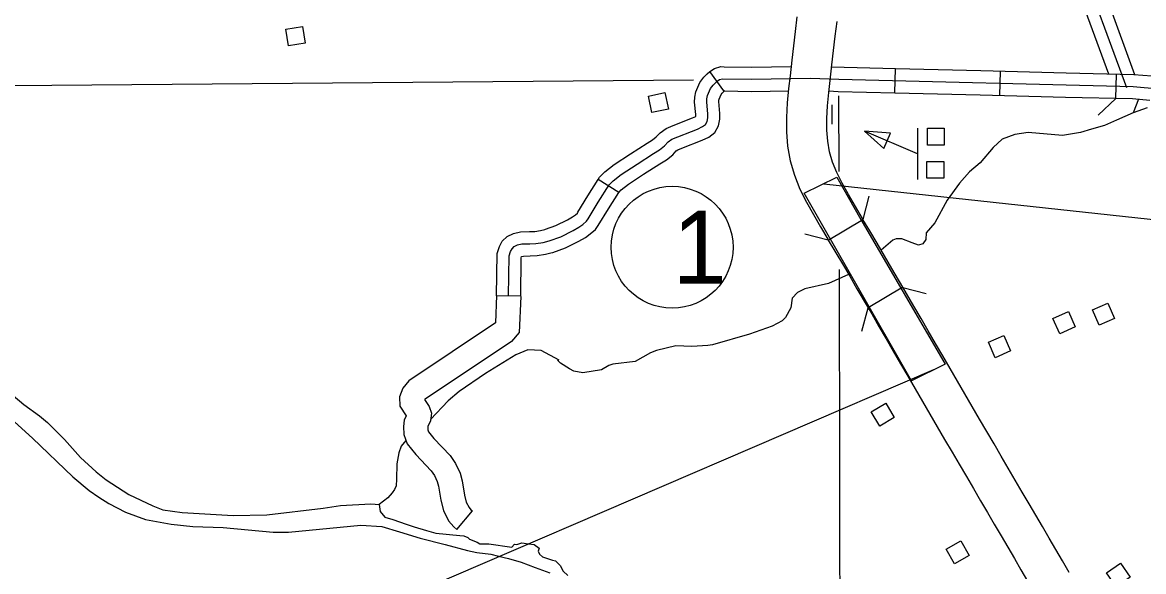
# Model space of a CAD drawing. Extents: x 1369885 to 1370219, y 379980 to 380218.
# Drawn here: x 1370027.37 to 1370054.99, y 380094.55 to 380108.07 of the extents above; entities that cross this region are included whole.
import ezdxf

# ---------------------------------------------------------------- set-up
doc = ezdxf.new("R2010")
doc.units = 0
for name, color, linetype in [('Default', 7, 'Continuous'), ('Level 10', 7, 'Continuous'), ('Level 32', 7, 'Continuous'), ('Level 35', 7, 'Continuous'), ('Level 37', 7, 'Continuous'), ('Level 38', 7, 'Continuous'), ('Level 45', 7, 'Continuous'), ('Level 46', 7, 'Continuous'), ('Level 5', 7, 'Continuous'), ('Level 56', 7, 'Continuous'), ('Page Text', 7, 'Continuous')]:
    doc.layers.add(name, color=color, linetype=linetype)

msp = doc.modelspace()

# ---------------------------------------------------------------- linework, layer by layer
at = {"layer": 'Default'}
msp.add_lwpolyline([(1370046.636, 380103.865), (1370047.441, 380104.259), (1370048.026, 380103.218), (1370050.106, 380099.662), (1370049.273, 380099.251)], close=True, dxfattribs=at)
msp.add_circle((1370043.38, 380102.537), 1.501, dxfattribs=at)
at = {"layer": 'Level 10'}
for points in [[(1370046.454, 380108.209), (1370046.412, 380107.854), (1370046.37, 380107.499), (1370046.328, 380107.147), (1370046.284, 380106.757), (1370046.25, 380106.446), (1370046.216, 380106.092), (1370046.196, 380105.734), (1370046.198, 380105.38), (1370046.226, 380105.025), (1370046.287, 380104.664), (1370046.391, 380104.309), (1370046.528, 380103.97), (1370046.69, 380103.651), (1370046.859, 380103.345), (1370047.034, 380103.042), (1370047.212, 380102.737), (1370047.227, 380102.712), (1370048.08, 380103.222)], [(1370048.08, 380103.222), (1370048.068, 380103.243), (1370047.894, 380103.542), (1370047.725, 380103.834), (1370047.569, 380104.116), (1370047.434, 380104.381), (1370047.332, 380104.636), (1370047.258, 380104.887), (1370047.214, 380105.148), (1370047.192, 380105.422), (1370047.191, 380105.71), (1370047.208, 380106.017), (1370047.239, 380106.345), (1370047.272, 380106.647), (1370047.316, 380107.033), (1370047.357, 380107.381), (1370047.4, 380107.737), (1370047.442, 380108.093)], [(1370049.064, 380101.551), (1370048.793, 380102.014), (1370048.613, 380102.326), (1370048.43, 380102.636), (1370048.248, 380102.942), (1370048.08, 380103.222)], [(1370047.227, 380102.712), (1370047.575, 380102.129), (1370047.754, 380101.824), (1370047.933, 380101.516), (1370048.207, 380101.046)], [(1370053.161, 380094.528), (1370052.999, 380094.812), (1370052.835, 380095.095), (1370052.672, 380095.377), (1370052.507, 380095.659), (1370052.341, 380095.94), (1370052.174, 380096.223), (1370052.004, 380096.51), (1370051.832, 380096.801), (1370051.661, 380097.094), (1370051.488, 380097.393), (1370051.311, 380097.697), (1370051.131, 380098.001), (1370050.952, 380098.305), (1370050.773, 380098.613), (1370050.593, 380098.926), (1370050.411, 380099.24), (1370050.228, 380099.552), (1370050.046, 380099.863), (1370049.867, 380100.17), (1370049.69, 380100.476), (1370049.512, 380100.782), (1370049.334, 380101.088), (1370049.154, 380101.397), (1370049.064, 380101.551), (1370048.207, 380101.046)], [(1370048.207, 380101.046), (1370048.296, 380100.895), (1370048.475, 380100.588), (1370048.652, 380100.282), (1370048.829, 380099.978), (1370049.007, 380099.67), (1370049.188, 380099.361), (1370049.37, 380099.05), (1370049.552, 380098.739), (1370049.732, 380098.428), (1370049.912, 380098.115), (1370050.094, 380097.803), (1370050.275, 380097.495), (1370050.453, 380097.194), (1370050.628, 380096.894), (1370050.801, 380096.594), (1370050.975, 380096.297), (1370051.148, 380096.005), (1370051.317, 380095.717), (1370051.485, 380095.434), (1370051.65, 380095.154), (1370051.812, 380094.877), (1370051.974, 380094.597), (1370052.137, 380094.316)]]:
    msp.add_lwpolyline(points, dxfattribs=at)
at = {"layer": 'Level 32'}
for p, q in [((1370048.87, 380106.341), (1370048.885, 380106.938)), ((1370051.451, 380106.277), (1370051.466, 380106.874)), ((1370054.31, 380106.2), (1370054.324, 380106.797))]:
    msp.add_line(p, q, dxfattribs=at)
for points in [[(1370047.31, 380106.977), (1370048.885, 380106.938)], [(1370048.885, 380106.938), (1370050.985, 380106.886)], [(1370050.985, 380106.886), (1370053.084, 380106.834)], [(1370046.778, 380106.702), (1370047.483, 380106.674), (1370054.738, 380106.495), (1370055.378, 380106.44)], [(1370053.084, 380106.834), (1370054.754, 380106.793), (1370055.2, 380106.755)], [(1370047.244, 380106.385), (1370047.473, 380106.376), (1370048.87, 380106.341)], [(1370048.87, 380106.341), (1370050.97, 380106.289)], [(1370050.97, 380106.289), (1370053.07, 380106.237)], [(1370053.07, 380106.237), (1370054.722, 380106.197), (1370055.15, 380106.16)]]:
    msp.add_lwpolyline(points, dxfattribs=at)
at = {"layer": 'Level 35'}
for points in [[(1370054.872, 380106.184), (1370054.735, 380105.847)], [(1370055.082, 380105.97), (1370054.735, 380105.847), (1370054.327, 380105.664), (1370054.028, 380105.535), (1370053.711, 380105.448), (1370053.437, 380105.365), (1370052.996, 380105.287), (1370052.151, 380105.365), (1370051.823, 380105.311), (1370051.513, 380105.202), (1370051.288, 380104.996), (1370050.966, 380104.615), (1370050.707, 380104.396), (1370050.457, 380104.117), (1370050.152, 380103.693), (1370049.851, 380103.142), (1370049.642, 380102.889), (1370049.633, 380102.728), (1370049.553, 380102.621), (1370049.446, 380102.586), (1370049.29, 380102.645), (1370049.037, 380102.747), (1370048.902, 380102.745), (1370048.821, 380102.711), (1370048.53, 380102.467)], [(1370047.729, 380101.868), (1370047.231, 380101.648), (1370046.651, 380101.514), (1370046.471, 380101.421), (1370046.341, 380101.282), (1370046.308, 380101.045), (1370046.172, 380100.81), (1370046.091, 380100.724), (1370045.845, 380100.597), (1370045.287, 380100.393), (1370044.373, 380100.138), (1370044.259, 380100.114), (1370043.866, 380100.09), (1370043.468, 380100.11), (1370042.995, 380099.996), (1370042.85, 380099.94), (1370042.471, 380099.721), (1370041.921, 380099.657), (1370041.823, 380099.626), (1370041.643, 380099.521), (1370041.181, 380099.447), (1370040.961, 380099.488), (1370040.852, 380099.54), (1370040.633, 380099.681), (1370040.555, 380099.76)], [(1370040.597, 380099.757), (1370040.157, 380099.997), (1370039.823, 380100.011), (1370039.529, 380099.89), (1370038.784, 380099.425), (1370038.13, 380098.987), (1370037.859, 380098.756), (1370037.43, 380098.297)], [(1370026.993, 380099.02), (1370027.405, 380098.662), (1370027.791, 380098.387), (1370027.99, 380098.221), (1370028.408, 380097.807), (1370028.807, 380097.361), (1370029.187, 380097.006), (1370029.439, 380096.806), (1370029.998, 380096.448), (1370030.583, 380096.167), (1370030.832, 380096.075), (1370031.307, 380096.002)], [(1370026.73, 380098.637), (1370027.62, 380097.839), (1370028.619, 380096.881), (1370029.014, 380096.55), (1370029.258, 380096.382), (1370029.501, 380096.226), (1370029.912, 380096.011), (1370030.402, 380095.831), (1370031.042, 380095.715), (1370031.575, 380095.663), (1370032.319, 380095.638), (1370033.554, 380095.52), (1370033.931, 380095.52), (1370035.714, 380095.697), (1370036.23, 380095.657), (1370036.662, 380095.53), (1370037.169, 380095.375), (1370037.791, 380095.219), (1370038.336, 380095.068), (1370038.569, 380095.023), (1370038.913, 380094.983), (1370039.103, 380094.931), (1370039.345, 380094.873), (1370039.657, 380094.781), (1370040.006, 380094.65), (1370040.369, 380094.518)], [(1370036.823, 380097.781), (1370036.702, 380097.636), (1370036.647, 380097.471), (1370036.596, 380097.206), (1370036.589, 380096.824), (1370036.584, 380096.666), (1370036.537, 380096.572), (1370036.484, 380096.493), (1370036.374, 380096.365), (1370036.166, 380096.199)], [(1370031.307, 380096.002), (1370032.564, 380095.932), (1370033.398, 380095.95), (1370034.783, 380096.114), (1370035.206, 380096.175), (1370035.959, 380096.222), (1370036.063, 380096.211), (1370036.166, 380096.199), (1370036.189, 380096.032), (1370036.305, 380095.894), (1370036.501, 380095.836), (1370036.827, 380095.715), (1370037.023, 380095.651), (1370037.329, 380095.559), (1370037.561, 380095.496), (1370038.147, 380095.438), (1370038.251, 380095.427), (1370038.345, 380095.386), (1370038.389, 380095.346), (1370038.573, 380095.277), (1370038.642, 380095.236), (1370038.867, 380095.236), (1370039.432, 380095.156), (1370039.493, 380095.227), (1370039.551, 380095.221), (1370039.676, 380095.258), (1370039.839, 380095.233), (1370039.983, 380095.221), (1370040.104, 380095.129), (1370040.081, 380095.054), (1370040.11, 380094.979), (1370040.19, 380094.91), (1370040.432, 380094.829), (1370040.507, 380094.812), (1370040.618, 380094.703), (1370040.694, 380094.562), (1370040.813, 380094.454)]]:
    msp.add_lwpolyline(points, dxfattribs=at)
at = {"layer": 'Level 37'}
for points in [[(1370048.23, 380103.798), (1370048.081, 380103.22)], [(1370047.225, 380102.714), (1370046.647, 380102.863)], [(1370049.065, 380101.549), (1370049.642, 380101.398)], [(1370048.054, 380100.47), (1370048.206, 380101.048)]]:
    msp.add_lwpolyline(points, dxfattribs=at)
at = {"layer": 'Level 38'}
for points in [[(1370054.324, 380106.797), (1370054.324, 380106.797)], [(1370054.31, 380106.2), (1370053.877, 380105.789)]]:
    msp.add_lwpolyline(points, dxfattribs=at)
at = {"layer": 'Level 45'}
for p, q in [((1370044.65, 380106.387), (1370044.307, 380106.867)), ((1370042.064, 380103.887), (1370041.557, 380104.202)), ((1370039.65, 380101.336), (1370039.053, 380101.343))]:
    msp.add_line(p, q, dxfattribs=at)
for points in [[(1370052.754, 380109.927), (1370053.05, 380109.996), (1370053.121, 380109.994), (1370053.246, 380109.934), (1370053.354, 380109.798), (1370054.57, 380106.474)], [(1370054.12, 380108.574), (1370054.771, 380106.792)], [(1370053.559, 380108.369), (1370054.13, 380106.808)], [(1370043.402, 380105.532), (1370043.884, 380105.721), (1370043.962, 380105.757), (1370043.962, 380105.758), (1370043.962, 380105.804), (1370043.933, 380106.109), (1370043.937, 380106.229), (1370043.966, 380106.367), (1370044.063, 380106.593), (1370044.161, 380106.726), (1370044.24, 380106.804), (1370044.307, 380106.867), (1370044.427, 380106.942), (1370044.582, 380106.985), (1370044.66, 380106.984)], [(1370044.66, 380106.984), (1370045.343, 380106.973), (1370046.311, 380106.991)], [(1370044.387, 380106.53), (1370044.447, 380106.589), (1370044.49, 380106.63), (1370044.548, 380106.666), (1370044.621, 380106.686), (1370045.343, 380106.674), (1370046.778, 380106.702)], [(1370039.351, 380101.339), (1370039.363, 380102.33), (1370039.398, 380102.434), (1370039.435, 380102.501), (1370039.49, 380102.555), (1370039.571, 380102.593), (1370039.68, 380102.619), (1370039.876, 380102.625), (1370040.026, 380102.63), (1370040.199, 380102.656), (1370040.352, 380102.697), (1370040.634, 380102.795), (1370040.939, 380102.953), (1370041.085, 380103.033), (1370041.181, 380103.099), (1370041.271, 380103.178), (1370041.31, 380103.235), (1370041.561, 380103.644), (1370041.829, 380104.074), (1370041.924, 380104.172), (1370042.128, 380104.33), (1370042.515, 380104.587), (1370042.918, 380104.847), (1370043.068, 380104.933), (1370043.192, 380105.034), (1370043.284, 380105.132), (1370043.376, 380105.201), (1370044.001, 380105.446), (1370044.131, 380105.507), (1370044.2, 380105.559), (1370044.24, 380105.634), (1370044.261, 380105.726), (1370044.261, 380105.818), (1370044.232, 380106.118), (1370044.235, 380106.193), (1370044.252, 380106.277), (1370044.324, 380106.444), (1370044.387, 380106.53)], [(1370043.619, 380104.976), (1370044.119, 380105.172), (1370044.285, 380105.25), (1370044.432, 380105.359), (1370044.523, 380105.529), (1370044.559, 380105.694), (1370044.559, 380105.832), (1370044.531, 380106.127), (1370044.532, 380106.157), (1370044.538, 380106.186), (1370044.585, 380106.295), (1370044.614, 380106.335), (1370044.654, 380106.374), (1370044.667, 380106.387), (1370044.65, 380106.387)], [(1370044.65, 380106.387), (1370045.344, 380106.376), (1370046.245, 380106.393)], [(1370041.557, 380104.202), (1370041.592, 380104.259), (1370041.724, 380104.395), (1370041.954, 380104.573), (1370042.351, 380104.837), (1370042.763, 380105.101), (1370042.898, 380105.179), (1370042.988, 380105.253), (1370043.084, 380105.355), (1370043.229, 380105.464), (1370043.402, 380105.532)], [(1370042.064, 380103.887), (1370042.065, 380103.889), (1370042.123, 380103.949), (1370042.303, 380104.088), (1370042.678, 380104.337), (1370043.073, 380104.592), (1370043.238, 380104.687), (1370043.395, 380104.815), (1370043.483, 380104.909), (1370043.523, 380104.938), (1370043.619, 380104.976)], [(1370040.242, 380102.976), (1370040.264, 380102.982), (1370040.516, 380103.069), (1370040.799, 380103.216), (1370040.928, 380103.287), (1370040.997, 380103.335), (1370041.047, 380103.379), (1370041.06, 380103.398), (1370041.307, 380103.801), (1370041.557, 380104.202)], [(1370040.395, 380102.399), (1370040.439, 380102.411), (1370040.752, 380102.52), (1370041.08, 380102.69), (1370041.243, 380102.779), (1370041.364, 380102.864), (1370041.495, 380102.978), (1370041.56, 380103.072), (1370041.815, 380103.487), (1370042.064, 380103.887)], [(1370039.053, 380101.343), (1370039.066, 380102.381), (1370039.124, 380102.556), (1370039.196, 380102.683), (1370039.316, 380102.804), (1370039.473, 380102.876), (1370039.641, 380102.916), (1370039.866, 380102.923), (1370039.998, 380102.928), (1370040.138, 380102.949), (1370040.242, 380102.976)], [(1370039.65, 380101.336), (1370039.661, 380102.28), (1370039.671, 380102.31), (1370039.719, 380102.321), (1370039.886, 380102.326), (1370040.054, 380102.333), (1370040.259, 380102.364), (1370040.395, 380102.399)]]:
    msp.add_lwpolyline(points, dxfattribs=at)
at = {"layer": 'Level 46'}
for points in [[(1370039.053, 380101.351), (1370039.026, 380100.674), (1370036.892, 380099.248), (1370036.743, 380099.067), (1370036.666, 380098.852), (1370036.673, 380098.628), (1370036.829, 380098.389), (1370036.78, 380098.276), (1370036.763, 380098.126), (1370036.77, 380097.924), (1370036.855, 380097.696), (1370037.062, 380097.435), (1370037.445, 380097.031), (1370037.525, 380096.915), (1370037.595, 380096.766), (1370037.627, 380096.655), (1370037.681, 380096.312), (1370037.746, 380096.053), (1370037.873, 380095.802), (1370037.999, 380095.649), (1370038.077, 380095.584), (1370038.459, 380096.043)], [(1370039.649, 380101.327), (1370039.614, 380100.435), (1370039.42, 380100.22), (1370037.296, 380098.8), (1370037.283, 380098.785), (1370037.394, 380098.617), (1370037.449, 380098.448), (1370037.425, 380098.264), (1370037.363, 380098.12), (1370037.361, 380098.102), (1370037.363, 380098.041), (1370037.381, 380097.993), (1370037.513, 380097.826), (1370037.91, 380097.408), (1370038.045, 380097.212), (1370038.155, 380096.977), (1370038.211, 380096.786), (1370038.266, 380096.431), (1370038.308, 380096.263), (1370038.376, 380096.13), (1370038.423, 380096.072), (1370038.459, 380096.043)]]:
    msp.add_lwpolyline(points, dxfattribs=at)
at = {"layer": 'Level 5'}
for points in [[(1370043.904, 380106.648), (1370026.108, 380106.504)], [(1370047.482, 380106.266), (1370047.486, 380104.4)], [(1370047.491, 380101.993), (1370047.513, 380091.942)]]:
    msp.add_lwpolyline(points, dxfattribs=at)
at = {"layer": 'Level 56'}
for points in [[(1370033.93, 380107.499), (1370033.866, 380107.908), (1370034.277, 380107.972), (1370034.34, 380107.563)], [(1370042.882, 380105.854), (1370042.796, 380106.259), (1370043.202, 380106.346), (1370043.288, 380105.941)], [(1370048.596, 380104.972), (1370048.756, 380105.345), (1370048.117, 380105.398)], [(1370049.67, 380105.053), (1370049.67, 380105.467), (1370050.085, 380105.467), (1370050.085, 380105.053)], [(1370049.658, 380104.237), (1370049.658, 380104.651), (1370050.073, 380104.651), (1370050.073, 380104.237)], [(1370053.9, 380100.615), (1370053.734, 380100.994), (1370054.115, 380101.16), (1370054.281, 380100.781)], [(1370052.933, 380100.404), (1370052.763, 380100.781), (1370053.141, 380100.952), (1370053.311, 380100.574)], [(1370051.339, 380099.818), (1370051.174, 380100.198), (1370051.554, 380100.363), (1370051.72, 380099.984)], [(1370048.498, 380098.131), (1370048.285, 380098.486), (1370048.641, 380098.7), (1370048.854, 380098.345)], [(1370050.337, 380094.741), (1370050.133, 380095.101), (1370050.495, 380095.306), (1370050.698, 380094.945)], [(1370054.318, 380094.179), (1370054.085, 380094.521), (1370054.429, 380094.754), (1370054.661, 380094.412)]]:
    msp.add_lwpolyline(points, close=True, dxfattribs=at)
for points in [[(1370047.314, 380106.041), (1370047.314, 380105.565)], [(1370049.421, 380104.839), (1370048.117, 380105.398)], [(1370049.421, 380105.47), (1370049.421, 380104.207)]]:
    msp.add_lwpolyline(points, dxfattribs=at)
at = {"layer": 'Page Text'}
for points in [[(1370047.12, 380104.1), (1370131.535, 380094.962)], [(1370049.822, 380099.52), (1369957.219, 380059.71)]]:
    msp.add_lwpolyline(points, dxfattribs=at)

# ---------------------------------------------------------------- texts
at = {"layer": 'Default'}
msp.add_text('1', height=1.8, dxfattribs=at).set_placement((1370043.389, 380101.637))

doc.saveas('drawing.dxf')
